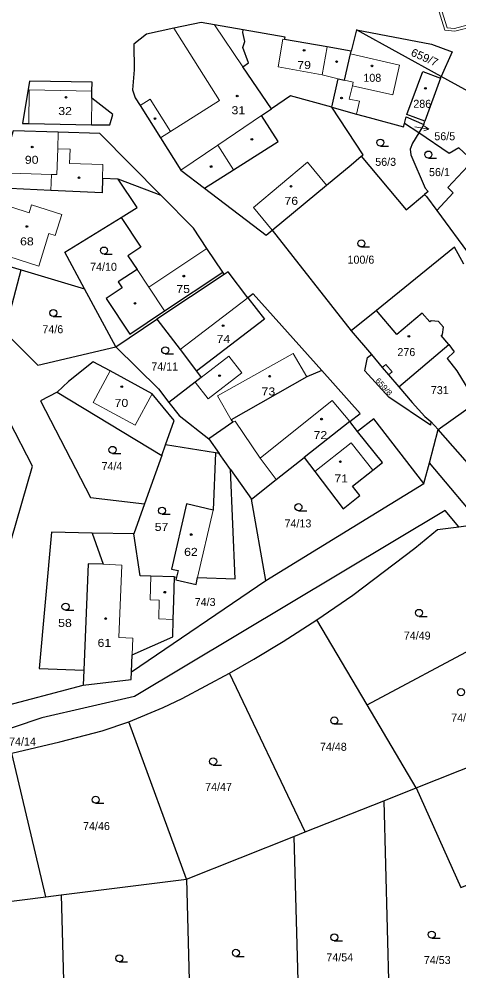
# Model space of a CAD drawing. Extents: x -758887 to -754328, y -1031688 to -1029144.
# Drawn here: x -756406 to -756312.6, y -1030649.6 to -1030447.4 of the extents above; entities that cross this region are included whole.
import ezdxf
from ezdxf.enums import TextEntityAlignment as Align

# ---------------------------------------------------------------- set-up
doc = ezdxf.new("R2010")
doc.units = 0
doc.header["$LTSCALE"] = 0.68
for name, color, linetype, lineweight in [('1', 7, 'Continuous', 25), ('13', 7, 'Continuous', 13), ('3', 7, 'Continuous', 25), ('4', 7, 'Continuous', 13), ('5', 7, 'Continuous', 25), ('7', 7, 'Continuous', 13)]:
    doc.layers.add(name, color=color, linetype=linetype, lineweight=lineweight)
doc.layers.add('2', color=7, linetype='Continuous')

msp = doc.modelspace()

# ---------------------------------------------------------------- linework, layer by layer
at = {"layer": '1'}
for p, q in [((-756316.47, -1030460), (-756319.8, -1030469.13)), ((-756316.47, -1030460), (-756316.33, -1030459.62)), ((-756320.04, -1030469.79), (-756319.8, -1030469.13)), ((-756321.14, -1030471.61), (-756324.16, -1030469.58)), ((-756320.04, -1030469.79), (-756321.14, -1030471.61)), ((-756321.14, -1030471.61), (-756322.48, -1030473.81)), ((-756319.15, -1030484.08), (-756319.89, -1030484.69)), ((-756352.23, -1030492.26), (-756335.46, -1030513.63)), ((-756409.04, -1030513.92), (-756405.56, -1030500.72)), ((-756362.42, -1030501.69), (-756362.75, -1030501.19)), ((-756385.48, -1030517.02), (-756392.11, -1030504.7)), ((-756385.48, -1030517.02), (-756376.72, -1030511.2)), ((-756325.37, -1030525.51), (-756314.73, -1030516.53)), ((-756317.02, -1030534.63), (-756308.95, -1030528.87)), ((-756335.78, -1030532.93), (-756345.49, -1030540.57)), ((-756334.1, -1030535.04), (-756335.78, -1030532.93)), ((-756318.87, -1030541.69), (-756317.02, -1030534.63)), ((-756309.74, -1030542.89), (-756317.02, -1030534.63)), ((-756364.31, -1030539.58), (-756374.9, -1030537.83)), ((-756365.73, -1030536.57), (-756363.5, -1030539.71)), ((-756375.71, -1030540.13), (-756379.34, -1030550.36)), ((-756320.02, -1030546.1), (-756318.87, -1030541.69)), ((-756353.6, -1030566.7), (-756320.02, -1030546.1)), ((-756353.6, -1030566.7), (-756356.66, -1030549.37)), ((-756379.34, -1030550.36), (-756381.62, -1030556.79)), ((-756317.11, -1030555.83), (-756312.59, -1030555.25)), ((-756312.59, -1030555.25), (-756310.14, -1030554.94)), ((-756381.62, -1030556.79), (-756390.51, -1030556.61)), ((-756373, -1030565.93), (-756372.57, -1030565.94)), ((-756382.13, -1030586.07), (-756353.6, -1030566.7)), ((-756332.11, -1030593.11), (-756296.39, -1030574.02)), ((-756392.25, -1030585.7), (-756392.38, -1030588.89)), ((-756412.92, -1030594.32), (-756392.38, -1030588.89)), ((-756370.44, -1030630.13), (-756382.69, -1030596.68)), ((-756321.68, -1030610.75), (-756284.35, -1030595.91)), ((-756328.56, -1030613.48), (-756327.16, -1030664.64)), ((-756347.65, -1030621.07), (-756346.44, -1030665.17)), ((-756370.44, -1030630.13), (-756369.47, -1030665.8)), ((-756397.1, -1030633.48), (-756396.2, -1030666.53))]:
    msp.add_line(p, q, dxfattribs=at)
for points in [[(-756358.39, -1030449.7), (-756364.5, -1030448.63), (-756367.36, -1030448.13), (-756373.12, -1030449.38), (-756378.98, -1030450.65), (-756381.66, -1030452.72), (-756381.53, -1030458.21), (-756381.94, -1030462.44), (-756381.35, -1030464.13), (-756380.31, -1030465.78), (-756375.95, -1030472.67), (-756371.64, -1030479.5), (-756366.63, -1030483.32)], [(-756352.42, -1030466.49), (-756358.47, -1030457.55), (-756357.27, -1030456.73), (-756358.5, -1030453.43), (-756358.03, -1030452.17), (-756358.5, -1030450.26), (-756358.39, -1030449.7)], [(-756335.49, -1030454.26), (-756340.61, -1030453.35), (-756349.62, -1030451.76), (-756349.53, -1030451.27), (-756358.39, -1030449.7)], [(-756316.33, -1030459.62), (-756334.37, -1030449.7), (-756335.49, -1030454.26)], [(-756334.37, -1030449.7), (-756318.42, -1030452.75), (-756314.04, -1030454.38), (-756316.33, -1030459.62)], [(-756339.59, -1030466.16), (-756338.21, -1030460.11), (-756336.91, -1030460.41), (-756335.63, -1030454.81), (-756335.49, -1030454.26)], [(-756319.8, -1030469.13), (-756323.62, -1030467.67), (-756320.27, -1030458.54), (-756316.47, -1030460)], [(-756295.16, -1030481.76), (-756296.9, -1030478.86), (-756296.56, -1030478.49), (-756301.26, -1030467.91), (-756316.33, -1030459.62)], [(-756339.59, -1030466.16), (-756348.37, -1030463.75), (-756352.42, -1030466.49)], [(-756366.63, -1030483.32), (-756360.46, -1030479.42), (-756350.98, -1030473.44), (-756354.49, -1030467.89), (-756352.42, -1030466.49)], [(-756339.59, -1030466.16), (-756334.34, -1030467.6), (-756331.65, -1030468.34), (-756324.37, -1030470.34), (-756324.16, -1030469.58)], [(-756333.32, -1030476.55), (-756332.94, -1030476.23), (-756339.59, -1030466.16)], [(-756324.16, -1030469.58), (-756323.78, -1030468.2), (-756320.04, -1030469.79)], [(-756375.85, -1030484.87), (-756388.84, -1030471.72), (-756397.68, -1030471.45), (-756407.23, -1030471.16), (-756409.98, -1030480.1), (-756410.97, -1030483.3)], [(-756309.65, -1030477.51), (-756312.58, -1030474.78), (-756314.65, -1030475.99), (-756321.14, -1030471.61)], [(-756322.48, -1030473.81), (-756322.93, -1030475.06), (-756322.78, -1030476.29), (-756319.74, -1030483.33), (-756319.15, -1030484.08)], [(-756352.23, -1030492.26), (-756340.7, -1030482.68), (-756335.5, -1030478.36), (-756333.32, -1030476.55)], [(-756333.32, -1030476.55), (-756323.82, -1030487.92), (-756319.89, -1030484.69)], [(-756309.65, -1030477.51), (-756314.96, -1030483.22), (-756313.79, -1030484.31), (-756317.3, -1030488.07), (-756309.97, -1030497.97)], [(-756384.93, -1030481.41), (-756388.28, -1030481.31), (-756388.37, -1030484.34), (-756399.29, -1030483.84), (-756410.97, -1030483.3)], [(-756362.75, -1030501.19), (-756366.11, -1030496.13), (-756368.95, -1030491.86), (-756375.85, -1030484.87), (-756384.93, -1030481.41)], [(-756384.33, -1030489.58), (-756380.9, -1030487.47), (-756384.93, -1030481.41)], [(-756410.97, -1030483.3), (-756412.16, -1030491.99), (-756415.96, -1030497.63), (-756405.56, -1030500.72), (-756392.11, -1030504.7)], [(-756366.63, -1030483.32), (-756353.5, -1030493.32), (-756352.23, -1030492.26)], [(-756319.89, -1030484.69), (-756319.48, -1030485.14), (-756317.3, -1030488.07)], [(-756392.11, -1030504.7), (-756396.3, -1030496.92), (-756384.33, -1030489.58)], [(-756384.33, -1030489.58), (-756380.13, -1030495.88), (-756382.89, -1030497.71), (-756380.96, -1030500.62), (-756384.93, -1030503.26), (-756384.11, -1030504.49), (-756387.53, -1030506.76), (-756382.5, -1030514.32), (-756375.12, -1030509.41), (-756362.75, -1030501.19)], [(-756311.54, -1030499.47), (-756313.51, -1030495.89), (-756330.09, -1030509.29)], [(-756357.39, -1030506.62), (-756361.58, -1030501.13), (-756362.42, -1030501.69), (-756376.72, -1030511.2)], [(-756357.39, -1030506.62), (-756353.9, -1030511.18), (-756368.32, -1030522.19)], [(-756341.74, -1030522.08), (-756356.31, -1030505.8), (-756357.39, -1030506.62)], [(-756314.73, -1030516.53), (-756316.34, -1030514.65), (-756316.07, -1030514.42), (-756315.89, -1030512.89), (-756316.93, -1030511.66), (-756318.52, -1030511.5), (-756318.79, -1030511.74), (-756320.4, -1030509.87), (-756325.77, -1030514.42), (-756330.09, -1030509.29), (-756335.46, -1030513.63), (-756331.19, -1030518.66)], [(-756376.72, -1030511.2), (-756371.8, -1030517.63), (-756368.32, -1030522.19)], [(-756409.04, -1030513.92), (-756401.99, -1030520.93), (-756385.48, -1030517.02)], [(-756385.48, -1030517.02), (-756376.38, -1030525.94), (-756374.17, -1030528.84)], [(-756314.73, -1030516.53), (-756313.61, -1030518.09), (-756315.11, -1030519.53), (-756313.06, -1030522.12), (-756308.95, -1030528.87)], [(-756318.62, -1030533.71), (-756327.49, -1030527.75), (-756332.61, -1030522.16), (-756331.98, -1030519.34), (-756331.19, -1030518.66)], [(-756331.19, -1030518.66), (-756328.87, -1030521.42), (-756327.54, -1030522.99), (-756325.37, -1030525.51)], [(-756368.32, -1030522.19), (-756367.3, -1030523.53), (-756368.62, -1030524.55), (-756374.17, -1030528.84)], [(-756341.74, -1030522.08), (-756344.89, -1030523.45), (-756360.95, -1030532.56), (-756360.58, -1030533.08), (-756365.73, -1030536.57)], [(-756335.78, -1030532.93), (-756333.58, -1030531.19), (-756341.74, -1030522.08)], [(-756325.37, -1030525.51), (-756322.54, -1030528.86), (-756319.83, -1030531.84), (-756318.53, -1030532.91)], [(-756397.93, -1030526.64), (-756401.47, -1030528.52), (-756390.86, -1030549.07), (-756379.34, -1030550.36)], [(-756374.17, -1030528.84), (-756372.02, -1030531.65), (-756365.73, -1030536.57)], [(-756419.67, -1030554.14), (-756414.24, -1030555.94), (-756407.72, -1030558.1), (-756403.18, -1030542.41), (-756408.06, -1030532.89)], [(-756320.02, -1030546.1), (-756330.69, -1030532.32), (-756334.1, -1030535.04)], [(-756317.02, -1030534.63), (-756318.53, -1030532.91), (-756318.62, -1030533.71)], [(-756345.49, -1030540.57), (-756343.22, -1030543.55), (-756337.2, -1030551.48), (-756333.62, -1030548.63), (-756335.18, -1030546.67), (-756330.87, -1030543.25), (-756328.85, -1030541.64), (-756334.1, -1030535.04)], [(-756364.31, -1030539.58), (-756364.77, -1030551.71), (-756370.43, -1030550.41), (-756373.62, -1030564.25), (-756372.25, -1030564.56), (-756372.57, -1030565.94)], [(-756372.57, -1030565.94), (-756372.7, -1030566.51), (-756368.41, -1030567.5), (-756368.08, -1030566.07), (-756360.09, -1030566.29), (-756361.1, -1030543.11), (-756363.5, -1030539.71), (-756364.31, -1030539.58)], [(-756361.1, -1030543.11), (-756356.66, -1030549.37), (-756351.42, -1030545.24), (-756345.49, -1030540.57)], [(-756276.81, -1030615.63), (-756276.9, -1030606.22), (-756295.51, -1030569.46), (-756318.87, -1030541.69)], [(-756312.59, -1030555.25), (-756315.52, -1030551.79), (-756381.49, -1030591.35), (-756401.18, -1030595.86), (-756437.11, -1030607.98), (-756464.98, -1030615.64), (-756516.89, -1030636.06), (-756515.63, -1030638.06), (-756495.42, -1030670.29), (-756493.95, -1030672.9)], [(-756342.8, -1030575.05), (-756335.14, -1030569.78), (-756321.96, -1030559.81), (-756317.11, -1030555.83)], [(-756390.51, -1030556.61), (-756399.14, -1030556.44), (-756401.77, -1030585.37), (-756392.25, -1030585.7)], [(-756390.51, -1030556.61), (-756388.17, -1030563.24), (-756391.3, -1030563.11), (-756392.25, -1030585.7)], [(-756373, -1030565.93), (-756377.99, -1030565.79), (-756380.29, -1030565.72), (-756381.62, -1030556.79)], [(-756382.13, -1030586.07), (-756381.98, -1030582.44), (-756373.36, -1030578.63), (-756373.26, -1030574.93), (-756373.14, -1030570.93), (-756373, -1030565.93)], [(-756361.34, -1030586.39), (-756356.17, -1030583.42), (-756349.95, -1030579.65), (-756342.8, -1030575.05)], [(-756321.68, -1030610.75), (-756332.11, -1030593.11), (-756342.8, -1030575.05)], [(-756400.29, -1030633.88), (-756397.1, -1030633.48), (-756370.44, -1030630.13), (-756347.65, -1030621.07), (-756345.22, -1030620.1), (-756361.34, -1030586.39)], [(-756392.38, -1030588.89), (-756382.2, -1030587.74), (-756382.13, -1030586.07)], [(-756382.69, -1030596.68), (-756375.38, -1030593.68), (-756371.38, -1030591.76), (-756361.34, -1030586.39)], [(-756407.55, -1030603.37), (-756397.34, -1030600.94), (-756388.34, -1030598.58), (-756382.69, -1030596.68)], [(-756457.99, -1030641.12), (-756431.26, -1030637.77), (-756426.06, -1030637.12), (-756400.29, -1030633.88), (-756407.55, -1030603.37)], [(-756345.22, -1030620.1), (-756328.56, -1030613.48), (-756321.68, -1030610.75)], [(-756321.68, -1030610.75), (-756312.2, -1030631.86), (-756276.22, -1030617.55)]]:
    msp.add_lwpolyline(points, dxfattribs=at)
for points in [[(-756390.54, -1030462.71), (-756390.5, -1030460.81), (-756403.8, -1030460.58), (-756405.25, -1030469.61), (-756403.95, -1030469.63), (-756390.65, -1030469.86), (-756386.75, -1030469.92), (-756386.08, -1030467.72), (-756390.56, -1030464.21)], [(-756374.9, -1030537.83), (-756373.07, -1030532.67), (-756377.71, -1030527), (-756386.66, -1030522.17), (-756390.29, -1030520.21), (-756395.51, -1030524.4), (-756397.93, -1030526.64), (-756375.71, -1030540.13)]]:
    msp.add_lwpolyline(points, close=True, dxfattribs=at)
at = {"layer": '13'}
for points in [[(-756317.15, -1030444.76), (-756315.55, -1030449.81), (-756313.48, -1030450), (-756309.41, -1030448.97), (-756305.55, -1030447.66), (-756295.4, -1030443.7)], [(-756305.75, -1030447.1), (-756309.59, -1030448.39), (-756313.52, -1030449.4), (-756315.09, -1030449.25), (-756316.59, -1030444.54)]]:
    msp.add_lwpolyline(points, dxfattribs=at)
at = {"layer": '3'}
for p, q in [((-756329.273, -1030474.41), (-756327.523, -1030474.41)), ((-756319.073, -1030476.95), (-756317.323, -1030476.95)), ((-756387.963, -1030497.34), (-756386.213, -1030497.34)), ((-756333.303, -1030495.83), (-756331.553, -1030495.83)), ((-756398.733, -1030510.6), (-756396.983, -1030510.6)), ((-756374.973, -1030518.52), (-756373.223, -1030518.52)), ((-756386.163, -1030539.69), (-756384.413, -1030539.69)), ((-756346.673, -1030551.85), (-756344.923, -1030551.85)), ((-756375.643, -1030552.6), (-756373.893, -1030552.6)), ((-756396.143, -1030572.99), (-756394.393, -1030572.99)), ((-756321.063, -1030574.31), (-756319.313, -1030574.31)), ((-756339.053, -1030597.16), (-756337.303, -1030597.16)), ((-756364.793, -1030605.87), (-756363.043, -1030605.87)), ((-756389.753, -1030614), (-756388.003, -1030614)), ((-756318.353, -1030642.65), (-756316.603, -1030642.65)), ((-756339.053, -1030643.23), (-756337.303, -1030643.23)), ((-756359.953, -1030646.52), (-756358.203, -1030646.52)), ((-756384.723, -1030647.68), (-756382.973, -1030647.68))]:
    msp.add_line(p, q, dxfattribs=at)
for centre in [(-756329.2729, -1030473.6598), (-756319.0729, -1030476.1998), (-756333.3029, -1030495.0798), (-756387.9629, -1030496.5898), (-756398.7329, -1030509.8498), (-756374.9729, -1030517.7698), (-756386.1629, -1030538.9398), (-756375.6429, -1030551.8498), (-756346.6729, -1030551.0998), (-756396.1429, -1030572.2398), (-756321.0629, -1030573.5598), (-756312.1529, -1030590.3998), (-756339.0529, -1030596.4098), (-756364.7929, -1030605.1198), (-756389.7529, -1030613.2498), (-756318.3529, -1030641.8998), (-756339.0529, -1030642.4798), (-756359.9529, -1030645.7698), (-756384.7229, -1030646.9298)]:
    msp.add_circle(centre, 0.75, dxfattribs=at)
at = {"layer": '4'}
for p, q in [((-756358.47, -1030457.55), (-756364.5, -1030448.63)), ((-756373.12, -1030449.38), (-756363.41, -1030464.75)), ((-756351.01, -1030457.6), (-756349.96, -1030451.7)), ((-756349.96, -1030451.7), (-756349.62, -1030451.76)), ((-756340.61, -1030453.35), (-756341.65, -1030459.26)), ((-756325.2, -1030457.19), (-756335.63, -1030454.81)), ((-756326.64, -1030463.53), (-756325.2, -1030457.19)), ((-756341.65, -1030459.26), (-756351.01, -1030457.6)), ((-756341.65, -1030459.26), (-756338.21, -1030460.11)), ((-756335.05, -1030460.83), (-756336.91, -1030460.41)), ((-756335.05, -1030460.83), (-756335.22, -1030461.57)), ((-756403.83, -1030462.48), (-756403.95, -1030469.63)), ((-756403.83, -1030462.48), (-756390.54, -1030462.71)), ((-756390.56, -1030464.21), (-756390.65, -1030469.86)), ((-756378.19, -1030464.44), (-756380.31, -1030465.78)), ((-756378.19, -1030464.44), (-756373.84, -1030471.33)), ((-756363.41, -1030464.75), (-756373.84, -1030471.33)), ((-756333.72, -1030464.88), (-756335.87, -1030464.4)), ((-756334.34, -1030467.6), (-756333.72, -1030464.88)), ((-756373.84, -1030471.33), (-756375.95, -1030472.67)), ((-756397.79, -1030474.95), (-756397.68, -1030471.45)), ((-756397.96, -1030480.46), (-756397.79, -1030474.95)), ((-756395.19, -1030475.03), (-756397.79, -1030474.95)), ((-756395.29, -1030478.13), (-756395.19, -1030475.03)), ((-756363.77, -1030474.17), (-756360.46, -1030479.42)), ((-756388.19, -1030478.34), (-756395.29, -1030478.13)), ((-756388.28, -1030481.31), (-756388.19, -1030478.34)), ((-756344.73, -1030477.84), (-756356.25, -1030487.42)), ((-756340.7, -1030482.68), (-756344.73, -1030477.84)), ((-756409.98, -1030480.1), (-756399.14, -1030480.43)), ((-756399.29, -1030483.84), (-756399.14, -1030480.43)), ((-756399.14, -1030480.43), (-756397.96, -1030480.46)), ((-756403.35, -1030486.9), (-756403.9, -1030488.59)), ((-756403.35, -1030486.9), (-756396.95, -1030488.9)), ((-756356.25, -1030487.42), (-756352.23, -1030492.26)), ((-756398.35, -1030493.38), (-756396.95, -1030488.9)), ((-756401.78, -1030499.91), (-756399.72, -1030492.96)), ((-756399.72, -1030492.96), (-756398.35, -1030493.38)), ((-756410.46, -1030497.18), (-756401.78, -1030499.91)), ((-756378.48, -1030504.35), (-756366.11, -1030496.13)), ((-756380.96, -1030500.62), (-756378.48, -1030504.35)), ((-756375.12, -1030509.41), (-756378.48, -1030504.35)), ((-756371.8, -1030517.63), (-756357.39, -1030506.62)), ((-756363.84, -1030527.48), (-756347.78, -1030518.46)), ((-756347.78, -1030518.46), (-756344.89, -1030523.45)), ((-756386.66, -1030522.17), (-756390.27, -1030528.87)), ((-756365.87, -1030528.11), (-756358.71, -1030522.58)), ((-756368.62, -1030524.55), (-756365.87, -1030528.11)), ((-756377.71, -1030527), (-756381.32, -1030533.7)), ((-756360.95, -1030532.56), (-756363.84, -1030527.48)), ((-756390.27, -1030528.87), (-756381.32, -1030533.7)), ((-756339.54, -1030528.45), (-756354.81, -1030540.71)), ((-756335.78, -1030532.93), (-756339.54, -1030528.45)), ((-756360.58, -1030533.08), (-756360.13, -1030532.8)), ((-756360.13, -1030532.8), (-756354.81, -1030540.71)), ((-756343.22, -1030543.55), (-756335.51, -1030537.42)), ((-756330.87, -1030543.25), (-756335.51, -1030537.42)), ((-756354.81, -1030540.71), (-756351.42, -1030545.24)), ((-756364.77, -1030551.71), (-756368.08, -1030566.07)), ((-756384.2, -1030563.41), (-756388.17, -1030563.24)), ((-756384.85, -1030578.8), (-756384.2, -1030563.41)), ((-756377.99, -1030565.79), (-756378.14, -1030570.79)), ((-756381.83, -1030578.92), (-756384.85, -1030578.8)), ((-756381.98, -1030582.44), (-756381.83, -1030578.92))]:
    msp.add_line(p, q, dxfattribs=at)
for points in [[(-756335.87, -1030464.4), (-756335.22, -1030461.57), (-756326.64, -1030463.53)], [(-756371.64, -1030479.5), (-756363.77, -1030474.17), (-756354.49, -1030467.89)], [(-756410.46, -1030497.18), (-756407.56, -1030487.4), (-756403.9, -1030488.59)], [(-756367.3, -1030523.53), (-756361.46, -1030519.02), (-756358.71, -1030522.58)], [(-756327.54, -1030522.99), (-756326.77, -1030522.33), (-756328.1, -1030520.76), (-756328.87, -1030521.42)], [(-756378.14, -1030570.79), (-756376.24, -1030570.84), (-756376.36, -1030574.84), (-756373.26, -1030574.93)]]:
    msp.add_lwpolyline(points, dxfattribs=at)
at = {"layer": '5'}
for centre in [(-756345.4768, -1030454.0592), (-756338.5668, -1030456.4592), (-756331.0568, -1030457.3592), (-756319.6968, -1030462.1492), (-756396.0268, -1030464.0392), (-756359.6868, -1030463.7692), (-756337.5268, -1030464.1892), (-756377.1268, -1030468.5492), (-756356.5668, -1030472.9692), (-756403.2168, -1030474.5992), (-756365.2268, -1030478.7392), (-756393.2668, -1030481.1292), (-756348.2468, -1030482.9392), (-756404.3568, -1030491.4792), (-756371.0168, -1030502.0292), (-756381.3968, -1030507.8092), (-756362.6768, -1030512.5392), (-756323.2268, -1030514.8192), (-756363.4368, -1030523.1692), (-756352.7768, -1030523.2792), (-756384.1868, -1030525.5192), (-756341.7668, -1030532.3992), (-756337.7768, -1030541.4392), (-756369.4568, -1030556.9092), (-756375.0568, -1030569.1592), (-756387.6068, -1030574.7592)]:
    msp.add_circle(centre, 0.175, dxfattribs=at)
at = {"layer": '7'}
for p, q in [((-756321.96, -1030470.31), (-756321.98, -1030470.31)), ((-756319.005, -1030470.831), (-756319.904, -1030470.164))]:
    msp.add_line(p, q, dxfattribs=at)
msp.add_lwpolyline([(-756321.96, -1030470.31), (-756319.005, -1030470.831), (-756320.078, -1030471.15)], dxfattribs=at)

# ---------------------------------------------------------------- texts
at = {"layer": '2'}
for s, height, rotation, width, p in [('659/7', 1.7, 336, 1.05, (-756320.2252, -1030456.3285)), ('659/8', 1.14, 312, 1.15, (-756328.9344, -1030525.8856))]:
    msp.add_text(s, height=height, rotation=rotation, dxfattribs=dict(at, width=width)).set_placement(p, align=Align.CENTER)
at = {"layer": '2', "width": 1.15}
for s, p in [('79', (-756345.47, -1030458.03)), ('32', (-756396.23, -1030467.81)), ('31', (-756359.44, -1030467.63)), ('90', (-756403.33, -1030478.16)), ('76', (-756348.2, -1030486.88)), ('68', (-756404.35, -1030495.49)), ('75', (-756371.16, -1030505.61)), ('74', (-756362.61, -1030516.22)), ('73', (-756353.06, -1030527.37)), ('70', (-756384.27, -1030529.81)), ('72', (-756342.01, -1030536.64)), ('71', (-756337.59, -1030545.86)), ('57', (-756375.75, -1030556.15)), ('62', (-756369.51, -1030561.45)), ('58', (-756396.26, -1030576.54)), ('61', (-756387.89, -1030580.78))]:
    msp.add_text(s, height=1.7, dxfattribs=at).set_placement(p, align=Align.CENTER)
at = {"layer": '2'}
for s, p in [('108', (-756330.989, -1030460.74)), ('286', (-756320.379, -1030466.27)), ('56/5', (-756315.6, -1030473.16)), ('56/3', (-756328.15, -1030478.6)), ('56/1', (-756316.73, -1030480.78)), ('100/6', (-756333.41, -1030499.38)), ('74/10', (-756388.07, -1030500.89)), ('74/6', (-756398.84, -1030514.15)), ('276', (-756323.759, -1030519.01)), ('74/11', (-756375.08, -1030522.07)), ('731', (-756316.659, -1030527.09)), ('74/4', (-756386.27, -1030543.24)), ('74/13', (-756346.78, -1030555.4)), ('74/3', (-756366.49, -1030572.1)), ('74/49', (-756321.45, -1030579.23)), ('74/50', (-756311.39, -1030596.65)), ('74/14', (-756405.28, -1030601.73)), ('74/48', (-756339.26, -1030602.85)), ('74/47', (-756363.64, -1030611.36)), ('74/46', (-756389.57, -1030619.69)), ('74/54', (-756337.9, -1030647.57)), ('74/53', (-756317.2, -1030648.15))]:
    msp.add_text(s, height=1.7, dxfattribs=at).set_placement(p, align=Align.CENTER)

doc.saveas('drawing.dxf')
